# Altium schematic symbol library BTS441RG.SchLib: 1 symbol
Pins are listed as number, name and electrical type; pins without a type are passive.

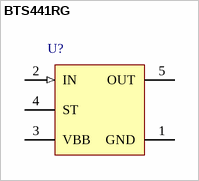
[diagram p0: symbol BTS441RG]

## BTS441RG
designator U?
Smart Power High-Side-Switch, 1 Channel, 17 A Load Current, -40 to 150 degC, PG-TO263-5-2, Reel, Green; Manufacturer: Infineon; PartNumber: BTS441RG; Channels: 1; Green: TRUE; Group: Automotive Qualified; Load Current (typ): 17 A; Ptot (max): 125 mW; Recommended Operating Voltage Max.: 41 V; Recommended Operating Voltage Min.: 4.75 V; RON @ 25degreesC: 20 mOhm; RON(max) @ 150degreesC: 37 mOhm; toff (max): 250 us; ton (max): 200 us
footprint INF-PG-TO263-5-2_N (DPAK, 5-Leads, Body 10x9.25mm, Pitch 1.7mm, IPC Medium Density)
footprint INF-PG-TO263-5-2_L (DPAK, 5-Leads, Body 10x9.25mm, Pitch 1.7mm, IPC High Density)
footprint INF-PG-TO263-5-2_M (DPAK, 5-Leads, Body 10x9.25mm, Pitch 1.7mm, IPC Low Density)
pins: 1 GND (power) "Logic ground.", 2 IN (in) "Input, activates the power switch in case of logical signal.", 3 VBB (power) "Positive power supply voltage, the tab is shorted to this pin", 4 ST (oc) "Diagnostic feedback", 5 OUT (power) "Output to the load."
